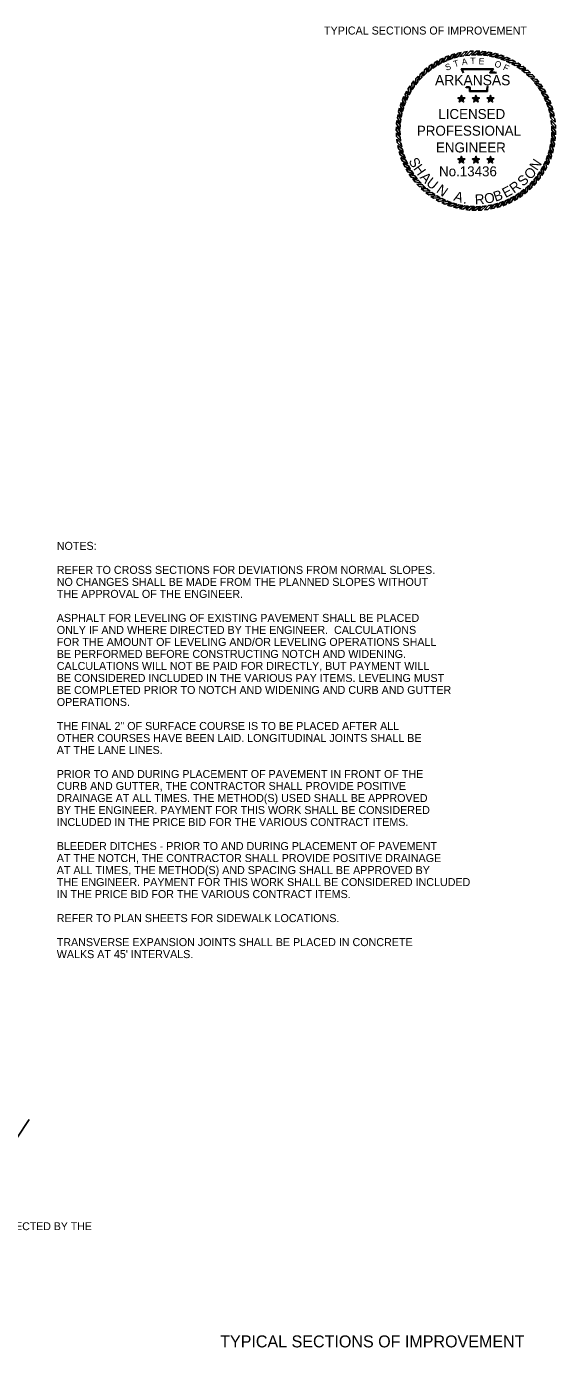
# Model space of a CAD drawing. Extents: x 1001270 to 1003428, y 1840152 to 1842912.
# Drawn here: x 1001659.5 to 1001699.1, y 1840291.9 to 1840391 of the extents above; entities that cross this region are included whole.
import ezdxf

# ---------------------------------------------------------------- set-up
doc = ezdxf.new("R2010")
doc.units = 0
for name, color, linetype in [('1', 7, 'Continuous'), ('19', 7, 'Continuous'), ('60', 7, 'Continuous'), ('Default', 7, 'Continuous'), ('G-ANNO-SYMB', 7, 'Continuous')]:
    doc.layers.add(name, color=color, linetype=linetype)

msp = doc.modelspace()

# ---------------------------------------------------------------- linework, layer by layer
at = {"layer": '19'}
msp.add_line((1001658.783, 1840307.652), (1001659.719, 1840309.033), dxfattribs=at)
at = {"layer": 'G-ANNO-SYMB'}
for points in [[(1001690.743, 1840388.6), (1001690.511, 1840388.491), (1001690.318, 1840388.076), (1001690.561, 1840388.21)], [(1001691.177, 1840388.775), (1001690.938, 1840388.684), (1001690.713, 1840388.286), (1001690.965, 1840388.4)], [(1001691.625, 1840388.915), (1001691.378, 1840388.843), (1001691.123, 1840388.464), (1001691.383, 1840388.558)], [(1001692.081, 1840389.02), (1001691.83, 1840388.967), (1001691.545, 1840388.609), (1001691.813, 1840388.682)], [(1001692.545, 1840389.088), (1001692.29, 1840389.055), (1001691.978, 1840388.721), (1001692.251, 1840388.773)], [(1001693.012, 1840389.12), (1001692.756, 1840389.107), (1001692.419, 1840388.798), (1001692.694, 1840388.828)], [(1001693.48, 1840389.115), (1001693.224, 1840389.122), (1001692.864, 1840388.84), (1001693.141, 1840388.849)], [(1001693.947, 1840389.073), (1001693.692, 1840389.1), (1001693.311, 1840388.848), (1001693.587, 1840388.835)], [(1001694.409, 1840388.995), (1001694.157, 1840389.042), (1001693.757, 1840388.82), (1001694.032, 1840388.786)], [(1001694.863, 1840388.88), (1001694.615, 1840388.947), (1001694.199, 1840388.758), (1001694.471, 1840388.702)], [(1001695.307, 1840388.731), (1001695.065, 1840388.817), (1001694.636, 1840388.661), (1001694.902, 1840388.584)], [(1001695.738, 1840388.547), (1001695.504, 1840388.652), (1001695.063, 1840388.53), (1001695.322, 1840388.432)], [(1001689.18, 1840387.58), (1001688.993, 1840387.404), (1001688.938, 1840386.95), (1001689.127, 1840387.152)], [(1001689.539, 1840387.881), (1001689.34, 1840387.72), (1001689.248, 1840387.271), (1001689.453, 1840387.458)], [(1001689.921, 1840388.152), (1001689.709, 1840388.007), (1001689.583, 1840387.567), (1001689.802, 1840387.737)], [(1001690.323, 1840388.392), (1001690.101, 1840388.265), (1001689.941, 1840387.836), (1001690.172, 1840387.988)], [(1001696.153, 1840388.33), (1001695.928, 1840388.453), (1001695.479, 1840388.366), (1001695.73, 1840388.248)], [(1001696.55, 1840388.081), (1001696.335, 1840388.221), (1001695.881, 1840388.169), (1001696.121, 1840388.032)], [(1001696.926, 1840387.802), (1001696.723, 1840387.958), (1001696.266, 1840387.942), (1001696.495, 1840387.787)], [(1001697.279, 1840387.494), (1001697.088, 1840387.666), (1001696.632, 1840387.686), (1001696.848, 1840387.512)], [(1001688.537, 1840386.9), (1001688.38, 1840386.696), (1001688.396, 1840386.239), (1001688.552, 1840386.469)], [(1001688.845, 1840387.252), (1001688.673, 1840387.062), (1001688.653, 1840386.605), (1001688.826, 1840386.822)], [(1001697.606, 1840387.159), (1001697.43, 1840387.345), (1001696.976, 1840387.401), (1001697.178, 1840387.211)], [(1001697.907, 1840386.799), (1001697.746, 1840386.999), (1001697.298, 1840387.09), (1001697.484, 1840386.885)], [(1001698.178, 1840386.417), (1001698.033, 1840386.629), (1001697.594, 1840386.755), (1001697.764, 1840386.536)], [(1001687.792, 1840385.712), (1001687.687, 1840385.477), (1001687.809, 1840385.037), (1001687.907, 1840385.296)], [(1001688.009, 1840386.127), (1001687.886, 1840385.902), (1001687.973, 1840385.453), (1001688.091, 1840385.703)], [(1001688.258, 1840386.523), (1001688.117, 1840386.309), (1001688.169, 1840385.854), (1001688.306, 1840386.095)], [(1001692.092, 1840385.532), (1001692.03, 1840385.616), (1001691.832, 1840385.616), (1001691.992, 1840385.5)], [(1001692.092, 1840385.532), (1001692.153, 1840385.616), (1001692.092, 1840385.805), (1001692.03, 1840385.616)], [(1001692.092, 1840385.532), (1001692.191, 1840385.5), (1001692.351, 1840385.616), (1001692.153, 1840385.616)], [(1001693.182, 1840385.532), (1001693.121, 1840385.616), (1001692.923, 1840385.616), (1001693.083, 1840385.5)], [(1001693.182, 1840385.532), (1001693.244, 1840385.616), (1001693.182, 1840385.805), (1001693.121, 1840385.616)], [(1001693.182, 1840385.532), (1001693.282, 1840385.5), (1001693.442, 1840385.616), (1001693.244, 1840385.616)], [(1001694.273, 1840385.532), (1001694.212, 1840385.616), (1001694.014, 1840385.616), (1001694.174, 1840385.5)], [(1001694.273, 1840385.532), (1001694.335, 1840385.616), (1001694.273, 1840385.805), (1001694.212, 1840385.616)], [(1001694.273, 1840385.532), (1001694.372, 1840385.5), (1001694.533, 1840385.616), (1001694.335, 1840385.616)], [(1001698.419, 1840386.015), (1001698.291, 1840386.238), (1001697.862, 1840386.398), (1001698.015, 1840386.166)], [(1001698.627, 1840385.596), (1001698.517, 1840385.828), (1001698.102, 1840386.021), (1001698.236, 1840385.778)], [(1001698.801, 1840385.161), (1001698.71, 1840385.401), (1001698.312, 1840385.626), (1001698.426, 1840385.373)], [(1001687.458, 1840384.837), (1001687.391, 1840384.589), (1001687.581, 1840384.173), (1001687.637, 1840384.445)], [(1001687.608, 1840385.281), (1001687.521, 1840385.039), (1001687.678, 1840384.609), (1001687.755, 1840384.876)], [(1001692.092, 1840385.532), (1001691.992, 1840385.5), (1001691.931, 1840385.311), (1001692.092, 1840385.428)], [(1001692.092, 1840385.532), (1001692.092, 1840385.428), (1001692.252, 1840385.311), (1001692.191, 1840385.5)], [(1001693.182, 1840385.532), (1001693.083, 1840385.5), (1001693.022, 1840385.311), (1001693.182, 1840385.428)], [(1001693.182, 1840385.532), (1001693.182, 1840385.428), (1001693.343, 1840385.311), (1001693.282, 1840385.5)], [(1001694.273, 1840385.532), (1001694.174, 1840385.5), (1001694.113, 1840385.311), (1001694.273, 1840385.428)], [(1001694.273, 1840385.532), (1001694.273, 1840385.428), (1001694.434, 1840385.311), (1001694.372, 1840385.5)], [(1001698.941, 1840384.714), (1001698.869, 1840384.96), (1001698.49, 1840385.216), (1001698.584, 1840384.955)], [(1001699.046, 1840384.257), (1001698.993, 1840384.509), (1001698.635, 1840384.793), (1001698.708, 1840384.526)], [(1001687.266, 1840383.921), (1001687.238, 1840383.666), (1001687.491, 1840383.284), (1001687.504, 1840383.561)], [(1001687.344, 1840384.383), (1001687.297, 1840384.13), (1001687.518, 1840383.73), (1001687.553, 1840384.005)], [(1001699.114, 1840383.794), (1001699.081, 1840384.048), (1001698.747, 1840384.36), (1001698.799, 1840384.088)], [(1001699.146, 1840383.327), (1001699.133, 1840383.583), (1001698.824, 1840383.92), (1001698.855, 1840383.645)], [(1001687.224, 1840383.454), (1001687.217, 1840383.198), (1001687.498, 1840382.837), (1001687.489, 1840383.114)], [(1001687.219, 1840382.986), (1001687.232, 1840382.729), (1001687.541, 1840382.392), (1001687.51, 1840382.668)], [(1001699.099, 1840382.392), (1001699.127, 1840382.647), (1001698.874, 1840383.028), (1001698.861, 1840382.751)], [(1001699.141, 1840382.858), (1001699.148, 1840383.115), (1001698.867, 1840383.475), (1001698.876, 1840383.198)], [(1001687.251, 1840382.518), (1001687.284, 1840382.264), (1001687.618, 1840381.952), (1001687.566, 1840382.224)], [(1001687.319, 1840382.055), (1001687.372, 1840381.804), (1001687.73, 1840381.519), (1001687.656, 1840381.786)], [(1001698.757, 1840381.032), (1001698.843, 1840381.273), (1001698.687, 1840381.703), (1001698.61, 1840381.437)], [(1001698.907, 1840381.476), (1001698.974, 1840381.723), (1001698.784, 1840382.139), (1001698.728, 1840381.868)], [(1001699.021, 1840381.93), (1001699.068, 1840382.182), (1001698.847, 1840382.582), (1001698.812, 1840382.307)], [(1001687.424, 1840381.598), (1001687.496, 1840381.352), (1001687.875, 1840381.096), (1001687.781, 1840381.357)], [(1001687.564, 1840381.151), (1001687.655, 1840380.911), (1001688.053, 1840380.686), (1001687.939, 1840380.939)], [(1001687.738, 1840380.717), (1001687.848, 1840380.485), (1001688.262, 1840380.291), (1001688.129, 1840380.534)], [(1001692.092, 1840380.964), (1001692.03, 1840381.048), (1001691.832, 1840381.048), (1001691.992, 1840380.931)], [(1001692.092, 1840380.964), (1001691.992, 1840380.931), (1001691.931, 1840380.743), (1001692.092, 1840380.859)], [(1001692.092, 1840380.964), (1001692.153, 1840381.048), (1001692.092, 1840381.236), (1001692.03, 1840381.048)], [(1001692.092, 1840380.964), (1001692.191, 1840380.931), (1001692.351, 1840381.048), (1001692.153, 1840381.048)], [(1001692.092, 1840380.964), (1001692.092, 1840380.859), (1001692.252, 1840380.743), (1001692.191, 1840380.931)], [(1001693.182, 1840380.964), (1001693.121, 1840381.048), (1001692.923, 1840381.048), (1001693.083, 1840380.931)], [(1001693.182, 1840380.964), (1001693.083, 1840380.931), (1001693.022, 1840380.743), (1001693.182, 1840380.859)], [(1001693.182, 1840380.964), (1001693.244, 1840381.048), (1001693.182, 1840381.236), (1001693.121, 1840381.048)], [(1001693.182, 1840380.964), (1001693.282, 1840380.931), (1001693.442, 1840381.048), (1001693.244, 1840381.048)], [(1001693.182, 1840380.964), (1001693.182, 1840380.859), (1001693.343, 1840380.743), (1001693.282, 1840380.931)], [(1001694.273, 1840380.964), (1001694.212, 1840381.048), (1001694.014, 1840381.048), (1001694.174, 1840380.931)], [(1001694.273, 1840380.964), (1001694.174, 1840380.931), (1001694.113, 1840380.743), (1001694.273, 1840380.859)], [(1001694.273, 1840380.964), (1001694.335, 1840381.048), (1001694.273, 1840381.236), (1001694.212, 1840381.048)], [(1001694.273, 1840380.964), (1001694.372, 1840380.931), (1001694.533, 1840381.048), (1001694.335, 1840381.048)], [(1001694.273, 1840380.964), (1001694.273, 1840380.859), (1001694.434, 1840380.743), (1001694.372, 1840380.931)], [(1001698.356, 1840380.186), (1001698.479, 1840380.411), (1001698.392, 1840380.86), (1001698.274, 1840380.609)], [(1001698.573, 1840380.601), (1001698.678, 1840380.835), (1001698.556, 1840381.275), (1001698.458, 1840381.016)], [(1001687.946, 1840380.297), (1001688.074, 1840380.074), (1001688.502, 1840379.914), (1001688.35, 1840380.146)], [(1001688.187, 1840379.895), (1001688.332, 1840379.683), (1001688.771, 1840379.557), (1001688.601, 1840379.776)], [(1001697.52, 1840379.06), (1001697.692, 1840379.25), (1001697.712, 1840379.707), (1001697.539, 1840379.491)], [(1001697.828, 1840379.413), (1001697.985, 1840379.616), (1001697.969, 1840380.073), (1001697.813, 1840379.844)], [(1001698.107, 1840379.789), (1001698.247, 1840380.004), (1001698.196, 1840380.458), (1001698.058, 1840380.217)], [(1001688.458, 1840379.513), (1001688.619, 1840379.313), (1001689.067, 1840379.222), (1001688.881, 1840379.427)], [(1001688.759, 1840379.154), (1001688.935, 1840378.967), (1001689.389, 1840378.911), (1001689.186, 1840379.101)], [(1001689.086, 1840378.819), (1001689.276, 1840378.647), (1001689.733, 1840378.627), (1001689.517, 1840378.8)], [(1001696.444, 1840378.161), (1001696.656, 1840378.305), (1001696.782, 1840378.745), (1001696.563, 1840378.575)], [(1001696.826, 1840378.432), (1001697.025, 1840378.593), (1001697.117, 1840379.041), (1001696.912, 1840378.854)], [(1001697.185, 1840378.732), (1001697.372, 1840378.908), (1001697.427, 1840379.362), (1001697.238, 1840379.16)], [(1001689.439, 1840378.511), (1001689.642, 1840378.354), (1001690.099, 1840378.37), (1001689.87, 1840378.526)], [(1001689.815, 1840378.231), (1001690.03, 1840378.091), (1001690.484, 1840378.143), (1001690.244, 1840378.28)], [(1001690.212, 1840377.982), (1001690.437, 1840377.859), (1001690.886, 1840377.947), (1001690.635, 1840378.065)], [(1001690.627, 1840377.765), (1001690.861, 1840377.66), (1001691.302, 1840377.783), (1001691.042, 1840377.88)], [(1001691.058, 1840377.581), (1001691.299, 1840377.495), (1001691.729, 1840377.652), (1001691.463, 1840377.729)], [(1001694.284, 1840377.293), (1001694.535, 1840377.346), (1001694.819, 1840377.703), (1001694.552, 1840377.63)], [(1001694.74, 1840377.397), (1001694.987, 1840377.47), (1001695.242, 1840377.849), (1001694.982, 1840377.755)], [(1001695.187, 1840377.537), (1001695.427, 1840377.629), (1001695.652, 1840378.027), (1001695.4, 1840377.912)], [(1001695.622, 1840377.712), (1001695.854, 1840377.822), (1001696.047, 1840378.236), (1001695.804, 1840378.103)], [(1001696.042, 1840377.92), (1001696.264, 1840378.048), (1001696.424, 1840378.476), (1001696.193, 1840378.324)], [(1001691.502, 1840377.432), (1001691.749, 1840377.365), (1001692.166, 1840377.555), (1001691.894, 1840377.611)], [(1001691.956, 1840377.318), (1001692.208, 1840377.27), (1001692.608, 1840377.492), (1001692.333, 1840377.527)], [(1001692.418, 1840377.239), (1001692.673, 1840377.212), (1001693.054, 1840377.464), (1001692.777, 1840377.477)], [(1001692.885, 1840377.198), (1001693.141, 1840377.19), (1001693.501, 1840377.472), (1001693.224, 1840377.463)], [(1001693.353, 1840377.193), (1001693.609, 1840377.206), (1001693.946, 1840377.514), (1001693.671, 1840377.484)], [(1001693.82, 1840377.224), (1001694.075, 1840377.257), (1001694.387, 1840377.592), (1001694.114, 1840377.54)]]:
    msp.add_lwpolyline(points, close=True, dxfattribs=at)
for points in [[(1001692.227, 1840387.486), (1001692.088, 1840387.787), (1001694.494, 1840387.789), (1001694.293, 1840387.536), (1001694.456, 1840387.538), (1001694.593, 1840387.54), (1001694.729, 1840387.525)], [(1001692.261, 1840387.502), (1001692.147, 1840387.749), (1001694.415, 1840387.751), (1001694.213, 1840387.497), (1001694.457, 1840387.5), (1001694.591, 1840387.502), (1001694.725, 1840387.487)], [(1001694.115, 1840386.478), (1001694.074, 1840386.444), (1001694.06, 1840386.394), (1001694.046, 1840386.27), (1001694.046, 1840386.103), (1001692.703, 1840386.103), (1001692.703, 1840386.328), (1001692.703, 1840386.378), (1001692.649, 1840386.394), (1001692.458, 1840386.394), (1001692.424, 1840386.446)], [(1001694.091, 1840386.507), (1001694.04, 1840386.466), (1001694.023, 1840386.402), (1001694.008, 1840386.272), (1001694.008, 1840386.141), (1001692.741, 1840386.141), (1001692.741, 1840386.328), (1001692.741, 1840386.406), (1001692.654, 1840386.433), (1001692.478, 1840386.433), (1001692.456, 1840386.467)]]:
    msp.add_lwpolyline(points, dxfattribs=at)

# ---------------------------------------------------------------- texts
at = {"layer": '1'}
msp.add_text('TYPICAL SECTIONS OF IMPROVEMENT', height=0.6, dxfattribs=at).set_placement((1001681.802, 1840390.365))
at = {"layer": '19'}
for s, p in [('NOTES:', (1001661.778, 1840351.737)), ('REFER TO CROSS SECTIONS FOR DEVIATIONS FROM NORMAL SLOPES.', (1001661.778, 1840349.937)), ('NO CHANGES SHALL BE MADE FROM THE PLANNED SLOPES WITHOUT', (1001661.778, 1840349.037)), ('THE APPROVAL OF THE ENGINEER.', (1001661.778, 1840348.137)), ('ASPHALT FOR LEVELING OF EXISTING PAVEMENT SHALL BE PLACED', (1001661.778, 1840346.337)), ('ONLY IF AND WHERE DIRECTED BY THE ENGINEER.  CALCULATIONS', (1001661.778, 1840345.437)), ('FOR THE AMOUNT OF LEVELING AND/OR LEVELING OPERATIONS SHALL', (1001661.778, 1840344.537)), ('BE PERFORMED BEFORE CONSTRUCTING NOTCH AND WIDENING.', (1001661.778, 1840343.637)), ('CALCULATIONS WILL NOT BE PAID FOR DIRECTLY, BUT PAYMENT WILL', (1001661.778, 1840342.737)), ('BE CONSIDERED INCLUDED IN THE VARIOUS PAY ITEMS. LEVELING MUST ', (1001661.778, 1840341.837)), ('BE COMPLETED PRIOR TO NOTCH AND WIDENING AND CURB AND GUTTER', (1001661.778, 1840340.937)), ('OPERATIONS. ', (1001661.778, 1840340.037)), ('THE FINAL 2" OF SURFACE COURSE IS TO BE PLACED AFTER ALL', (1001661.778, 1840338.237)), ('AT THE LANE LINES.', (1001661.778, 1840336.437)), ('OTHER COURSES HAVE BEEN LAID. LONGITUDINAL JOINTS SHALL BE', (1001661.778, 1840337.337)), ('PRIOR TO AND DURING PLACEMENT OF PAVEMENT IN FRONT OF THE', (1001661.778, 1840334.637)), ('CURB AND GUTTER, THE CONTRACTOR SHALL PROVIDE POSITIVE', (1001661.778, 1840333.737)), ('DRAINAGE AT ALL TIMES. THE METHOD(S) USED SHALL BE APPROVED', (1001661.778, 1840332.837)), ('BY THE ENGINEER. PAYMENT FOR THIS WORK SHALL BE CONSIDERED', (1001661.778, 1840331.937)), ('INCLUDED IN THE PRICE BID FOR THE VARIOUS CONTRACT ITEMS.', (1001661.778, 1840331.037)), ('BLEEDER DITCHES - PRIOR TO AND DURING PLACEMENT OF PAVEMENT', (1001661.778, 1840329.237)), ('AT THE NOTCH, THE CONTRACTOR SHALL PROVIDE POSITIVE DRAINAGE', (1001661.778, 1840328.337)), ('AT ALL TIMES, THE METHOD(S) AND SPACING SHALL BE APPROVED BY', (1001661.778, 1840327.437)), ('THE ENGINEER. PAYMENT FOR THIS WORK SHALL BE CONSIDERED INCLUDED', (1001661.778, 1840326.537)), ('IN THE PRICE BID FOR THE VARIOUS CONTRACT ITEMS.', (1001661.778, 1840325.637)), ('REFER TO PLAN SHEETS FOR SIDEWALK LOCATIONS.', (1001661.778, 1840323.837)), ('TRANSVERSE EXPANSION JOINTS SHALL BE PLACED IN CONCRETE', (1001661.778, 1840322.037)), ("WALKS AT 45' INTERVALS.", (1001661.778, 1840321.137))]:
    msp.add_text(s, height=0.6, dxfattribs=at).set_placement(p)
at = {"layer": '60'}
msp.add_text('TYPICAL SECTIONS OF IMPROVEMENT', height=0.9, dxfattribs=at).set_placement((1001674.019, 1840291.957))
at = {"layer": 'Default'}
msp.add_text('TO BE USED IF AND WHERE DIRECTED BY THE ', height=0.59001, rotation=359.99538, dxfattribs=at).set_placement((1001646.345, 1840300.748))
at = {"layer": 'G-ANNO-SYMB'}
for s, height, rotation, p in [('A', 0.475, 8.67877, (1001692.153, 1840388.065)), ('T', 0.475, 1.47887, (1001692.766, 1840388.16)), ('E', 0.475, 356.67203, (1001693.374, 1840388.146)), ('S', 0.475, 19.77256, (1001690.973, 1840387.644)), ('T', 0.475, 16.90148, (1001691.577, 1840387.915)), ('O', 0.475, 341.2218, (1001694.526, 1840387.983)), ('F', 0.475, 335.36282, (1001695.166, 1840387.733)), ('ARKANSAS', 0.7747, 360, (1001690.12, 1840386.564)), ('LICENSED', 0.75, 360, (1001690.361, 1840384.035)), ('PROFESSIONAL', 0.75, 360, (1001688.754, 1840382.781)), ('ENGINEER', 0.75, 360, (1001690.182, 1840381.527)), ('S', 0.75, 298.16364, (1001688.115, 1840380.896)), ('H', 0.75, 305.61905, (1001688.456, 1840380.309)), ('N', 0.75, 56.10067, (1001697.756, 1840380.113)), ('A', 0.75, 313.44722, (1001688.933, 1840379.624)), ('U', 0.75, 320.90262, (1001689.4, 1840379.135)), ('No.13436', 0.747, 360, (1001690.419, 1840379.739)), ('S', 0.75, 43.48784, (1001696.72, 1840378.94)), ('O', 0.75, 44.77573, (1001697.236, 1840379.437)), ('N', 0.75, 324.93262, (1001690.156, 1840378.576)), ('B', 0.75, 18.88501, (1001694.639, 1840377.827)), ('E', 0.75, 27.83149, (1001695.397, 1840378.098)), ('R', 0.75, 35.65967, (1001696.031, 1840378.43)), ('A', 0.75, 343.09908, (1001691.463, 1840377.933)), ('.', 0.75, 351.30002, (1001692.2, 1840377.714)), ('R', 0.75, 3.22866, (1001693.12, 1840377.619)), ('O', 0.75, 11.42961, (1001693.887, 1840377.668))]:
    msp.add_text(s, height=height, rotation=rotation, dxfattribs=at).set_placement(p)

doc.saveas('drawing.dxf')
